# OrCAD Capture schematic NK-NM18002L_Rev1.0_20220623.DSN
size A4; title: Singl Fan system demo board; rev: V1.0
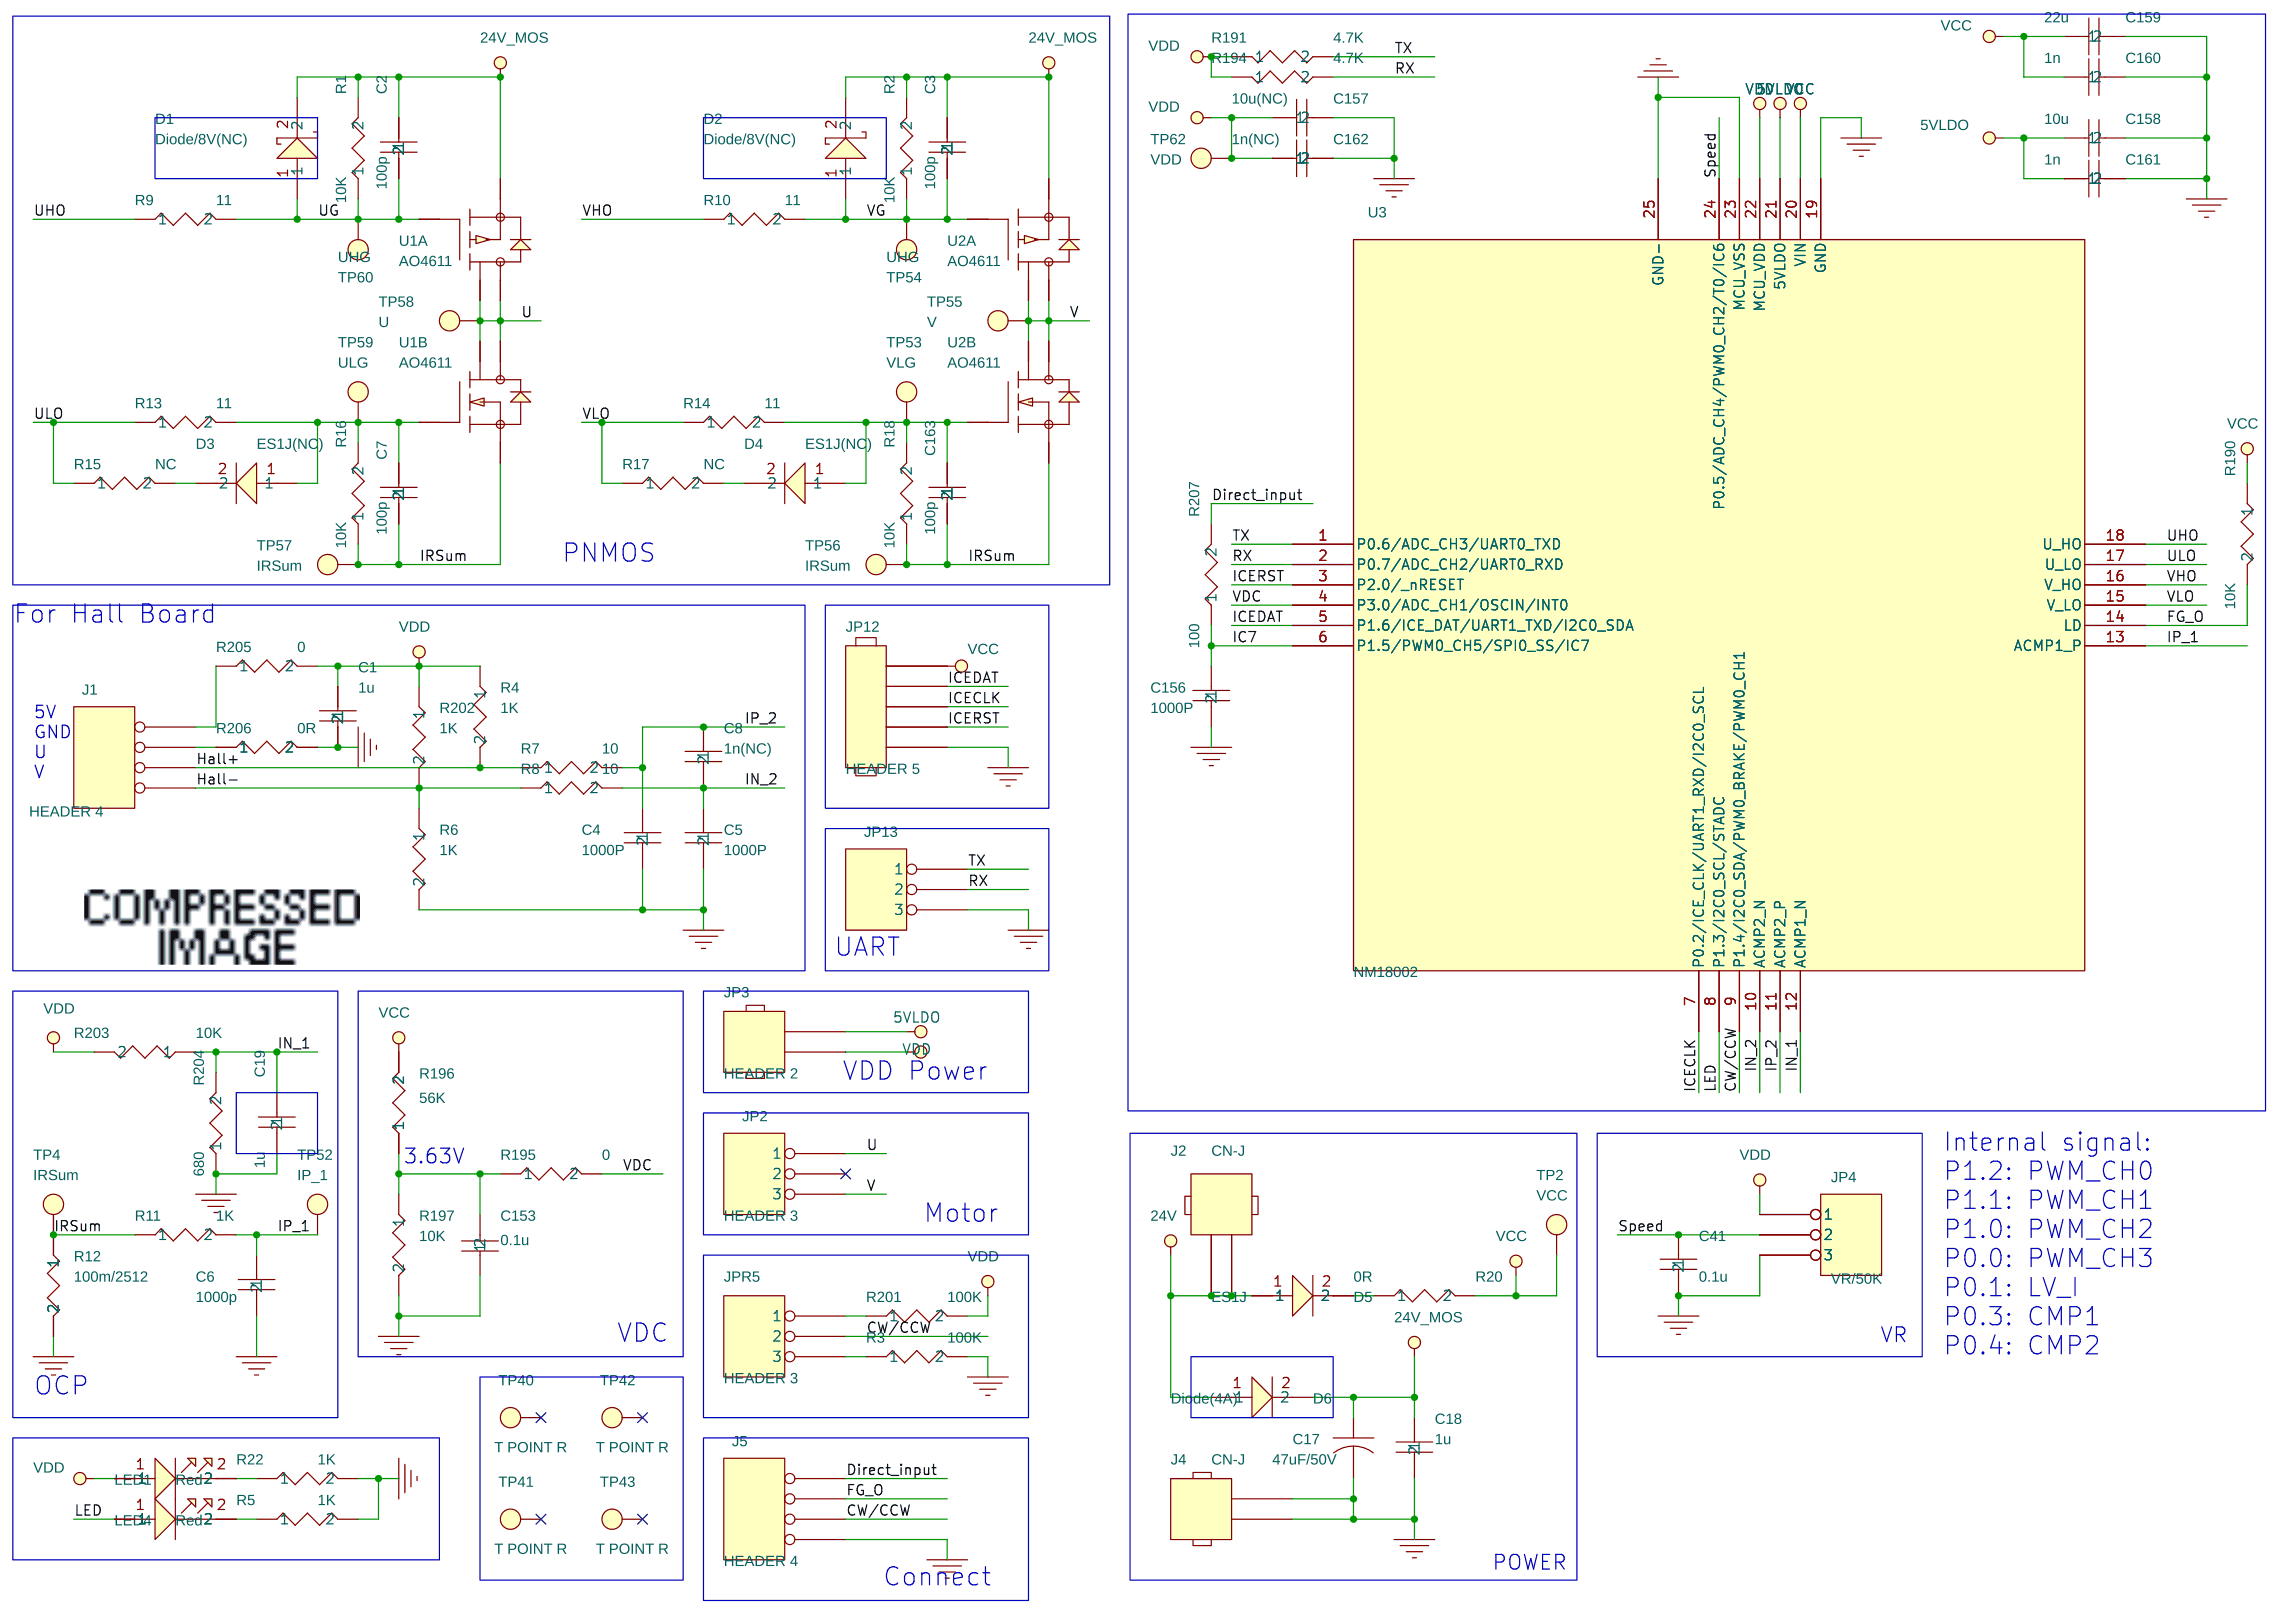
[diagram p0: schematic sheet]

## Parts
C1  1u  [C0603]
C2  100p  [C0805]
C3  100p  [C0805]
C4  1000P  [C0603]
C5  1000P  [C0603]
C6  1000p  [C0603]
C7  100p  [C0805]
C8  1n(NC)  [C0603]
C17  47uF/50V  [CAP_10.5_0.5]
C18  1u  [C0805]
C19  1u  [C0603]
C41  0.1u  [C0603]
C153  0.1u  [C0603]
C156  1000P  [C0603]
C157  10u(NC)  [C0805]
C158  10u  [C0805]
C159  22u  [C0805]
C160  1n  [C0603]
C161  1n  [C0603]
C162  1n(NC)  [C0603]
C163  100p  [C0805]
D1  Diode/8V(NC)  [RB060L]
D2  Diode/8V(NC)  [RB060L]
D3  ES1J(NC)  [RB060L]
D4  ES1J(NC)  [RB060L]
D5  ES1J  [RB060L]
D6  Diode(4A)  [RB060L]
J1  HEADER 4  [header1x4]
J2  CN-J  [CN-J]
J4  CN-J  [CN-J]
J5  HEADER 4  [header1x4]
JP2  HEADER 3  [header3]
JP3  HEADER 2  [HEADER1x2\2.54]
JP4  VR/50K  [VR-10X10.3]
JP12  HEADER 5  [header1x5]
JP13  HEADER 3  [header3]
JPR5  HEADER 3  [HEADER3]
LED1  Red  [LED0805]
LED4  Red  [LED0805]
R1  10K  [R0805]
R2  10K  [R0805]
R3  100K  [R0603]
R4  1K  [R0603]
R5  1K  [R0603]
R6  1K  [R0603]
R7  10  [R0603]
R8  10  [R0603]
R9  11  [R0805]
R10  11  [R0805]
R11  1K  [R0603]
R12  100m/2512  [2512]
R13  11  [R0805]
R14  11  [R0805]
R15  NC  [R0805]
R16  10K  [R0805]
R17  NC  [R0805]
R18  10K  [R0805]
R20  0R  [R0805]
R22  1K  [R0603]
R190  10K  [R0603]
R191  4.7K  [R0603]
R194  4.7K  [R0603]
R195  0  [R0603]
R196  56K  [R0603]
R197  10K  [R0603]
R201  100K  [R0603]
R202  1K  [R0603]
R203  10K  [R0603]
R204  680  [R0603]
R205  0  [R0603]
R206  0R  [R0603]
R207  100  [R0603]
TP2  VCC  [SIP\1P]
TP4  IRSum  [SIP\1P]
TP40  T POINT R  [GND_H]
TP41  T POINT R  [GND_H]
TP42  T POINT R  [GND_H]
TP43  T POINT R  [GND_H]
TP52  IP_1  [SIP\1P]
TP53  VLG  [SIP\1P]
TP54  UHG  [SIP\1P]
TP55  V  [SIP\1P]
TP56  IRSum  [SIP\1P]
TP57  IRSum  [SIP\1P]
TP58  U  [SIP\1P]
TP59  ULG  [SIP\1P]
TP60  UHG  [SIP\1P]
TP62  VDD  [SIP\1P]
U1  AO4611  [SOP8_PDS3712]  (sections A,B)
U2  AO4611  [SOP8_PDS3712]  (sections A,B)
U3  NM18002  [QFN-0.5MM-24P]

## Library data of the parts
C1 = C_0.1u_7
C2 = C_20p
C3 = C_20p_7
C4 = C_0.1u_5
C5 = C_0.1u_6
C6 = C_20p_2
C7 = C_20p_8
C8 = C_0.1u_8
C17 = C_10uF_10V
C18 = C_0.1u_3
C19 = C_20p_5
C41 = C_0.1u_10
C153 = C_0.1u_1
C156 = C_0.1u
C157 = C_0.1u_9
C158 = C_0.1u_2
C159 = C_0.1u_4
C160 = C_20p_1
C161 = C_20p_4
C162 = C_20p_6
C163 = C_20p_3
D1 = ESJ_1
D2 = ESJ
D3 = D_SS24A_5_3
D4 = D_SS24A_5
D5 = D_SS24A_5_2
D6 = D_SS24A_5_1
J1 J5 = HEADER_4
J2 J4 JP3 = HEADER_2
JP2 = HEADER_3_1
JP4 = HEADER_3_3
JP12 = HEADER_5
JP13 = HEADER_3_2
JPR5 = HEADER_3
LED1 = LED_GREEN_1
LED4 = LED_GREEN
R1 = R_1K_3
R2 = R_1K_2
R3 = R_1K_4
R4 = R_4.7K_3
R5 = R_33_2
R6 = R_4.7K_1
R7 = R_33
R8 = R_33_1
R9 = R_1K_6
R10 = R_1K_12
R11 = R_1K_13
R12 = R_0_1
R13 = R_1K_7
R14 = R_1K_5
R15 = R_1K_11
R16 = R_1K_1
R17 = R_1K_8
R18 = R_1K_10
R20 = R_33_6
R22 = R_33_7
R190 = R_33_3
R191 = R_100K
R194 = R_100K_1
R195 = R_0
R196 = R_4.7K_2
R197 = R_10K_1
R201 = R_1K
R202 = R_4.7K
R203 = R_1K_9
R204 = R_10K
R205 = R_33_4
R206 = R_33_5
R207 = R_33_8
TP2 TP4 TP40-TP43 TP52-TP60 TP62 = T_POINT_R
U1 U2 = PDS3712
U3 = NM1230L_4

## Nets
5VLDO: C158.1 C161.1 JP3.1 U3.21(5VLDO)
24V: D5.1 D6.1 J2.1 J2.2
24V_MOS: C2.1 C3.1 C17.1 C18.1 D1.2 D2.2 D6.2 R1.2 R2.2 R196.2 U1.3 U2.3
GND: C1.2 C4.2 C5.2 C6.2 C17.2 C18.2 C19.2 C41.2 C153.1 C156.2 C157.2 C158.2 C159.2 C160.2 C161.2 C162.2 J4.1 J4.2 J5.4 JP4.3 JP12.5 JP13.3 R3.2 R5.2 R6.2 R12.2 R22.2 R197.2 R204.1 R206.2 U3.19(GND) U3.23(MCU_VSS) U3.25(GND-)
VCC: C159.1 C160.1 R20.2 R190.1 TP2.1(TP) U3.20(VIN)
VDD: C1.1 C157.1 C162.1 JP3.2 JP4.1 JP12.1 LED1.1 R4.1 R191.1 R194.1 R201.2 R202.1 R203.2 R205.2 TP62.1(TP) U3.22(MCU_VDD)
CW/CCW: J5.3 JPR5.2 U3.9(P1.4/I2C0_SDA/PWM0_BRAKE/PWM0_CH1)
Direct_input: J5.1 R207.2
FG_O: J5.2 R190.2 U3.14(LD)
Hall+: J1.3 R4.2 R7.1
Hall-: J1.4 R6.1 R8.1 R202.2
IC7: C156.1 R207.1 U3.6(P1.5/PWM0_CH5/SPI0_SS/IC7)
ICECLK: JP12.3 U3.7(P0.2/ICE_CLK/UART1_RXD/I2C0_SCL)
ICEDAT: JP12.2 U3.5(P1.6/ICE_DAT/UART1_TXD/I2C0_SDA)
ICERST: JP12.4 U3.3(P2.0/_nRESET)
IN_1: C19.1 R203.1 R204.2 U3.12(ACMP1_N)
IN_2: C5.1 C8.2 R8.2 U3.10(ACMP2_N)
IP_1: C6.1 R11.2 TP52.1(TP) U3.13(ACMP1_P)
IP_2: C4.1 C8.1 R7.2 U3.11(ACMP2_P)
IRSum: C7.2 C163.2 R11.1 R12.1 R16.1 R18.1 TP4.1(TP) TP56.1(TP) TP57.1(TP) U1.1 U2.1
LED: LED4.1 U3.8(P1.3/I2C0_SCL/STADC)
RX: JP13.2 R194.2 U3.2(P0.7/ADC_CH2/UART0_RXD)
Speed: C41.1 JP4.2 U3.24(P0.5/ADC_CH4/PWM0_CH2/T0/IC6)
TX: JP13.1 R191.2 U3.1(P0.6/ADC_CH3/UART0_TXD)
U: JP2.1 TP58.1(TP) U1.5 U1.6 U1.7 U1.8
UG: C2.2 D1.1 R1.1 R9.2 TP60.1(TP) U1.4
UHO: R9.1 U3.18(U_HO)
ULO: R13.1 R15.1 U3.17(U_LO)
V: JP2.3 TP55.1(TP) U2.5 U2.6 U2.7 U2.8
VDC: R195.2 U3.4(P3.0/ADC_CH1/OSCIN/INT0)
VG: C3.2 D2.1 R2.1 R10.2 TP54.1(TP) U2.4
VHO: R10.1 U3.16(V_HO)
VLO: R14.1 R17.1 U3.15(V_LO)
N255233: C7.1 D3.1 R13.2 R16.2 TP59.1(TP) U1.2
N261871: C163.1 D4.1 R14.2 R18.2 TP53.1(TP) U2.2
N392053: D3.2 R15.2
N392213: D4.2 R17.2
N439745: D5.2 R20.1
N483437: LED1.2 R22.1
N753042: C153.2 R195.1 R196.1 R197.1
N753943: JPR5.1 R201.1
N753947: JPR5.3 R3.1
N756684: LED4.2 R5.1
N757926: J1.2 R206.1
N757930: J1.1 R205.1

Not connected (* = marked no-connect by the designer): JP2 2*; TP40 1(TP)*; TP41 1(TP)*; TP42 1(TP)*; TP43 1(TP)*

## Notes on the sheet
- PNMOS
- For Hall Board
- 5V
  GND
  U
  V
- UART
- VDD Power
- Internal signal:
  P1.2: PWM_CH0
  P1.1: PWM_CH1
  P1.0: PWM_CH2
  P0.0: PWM_CH3
  P0.1: LV_I
  P0.3: CMP1
  P0.4: CMP2
- 3.63V
- Motor
- VDC
- VR
- OCP
- POWER
- Connect
